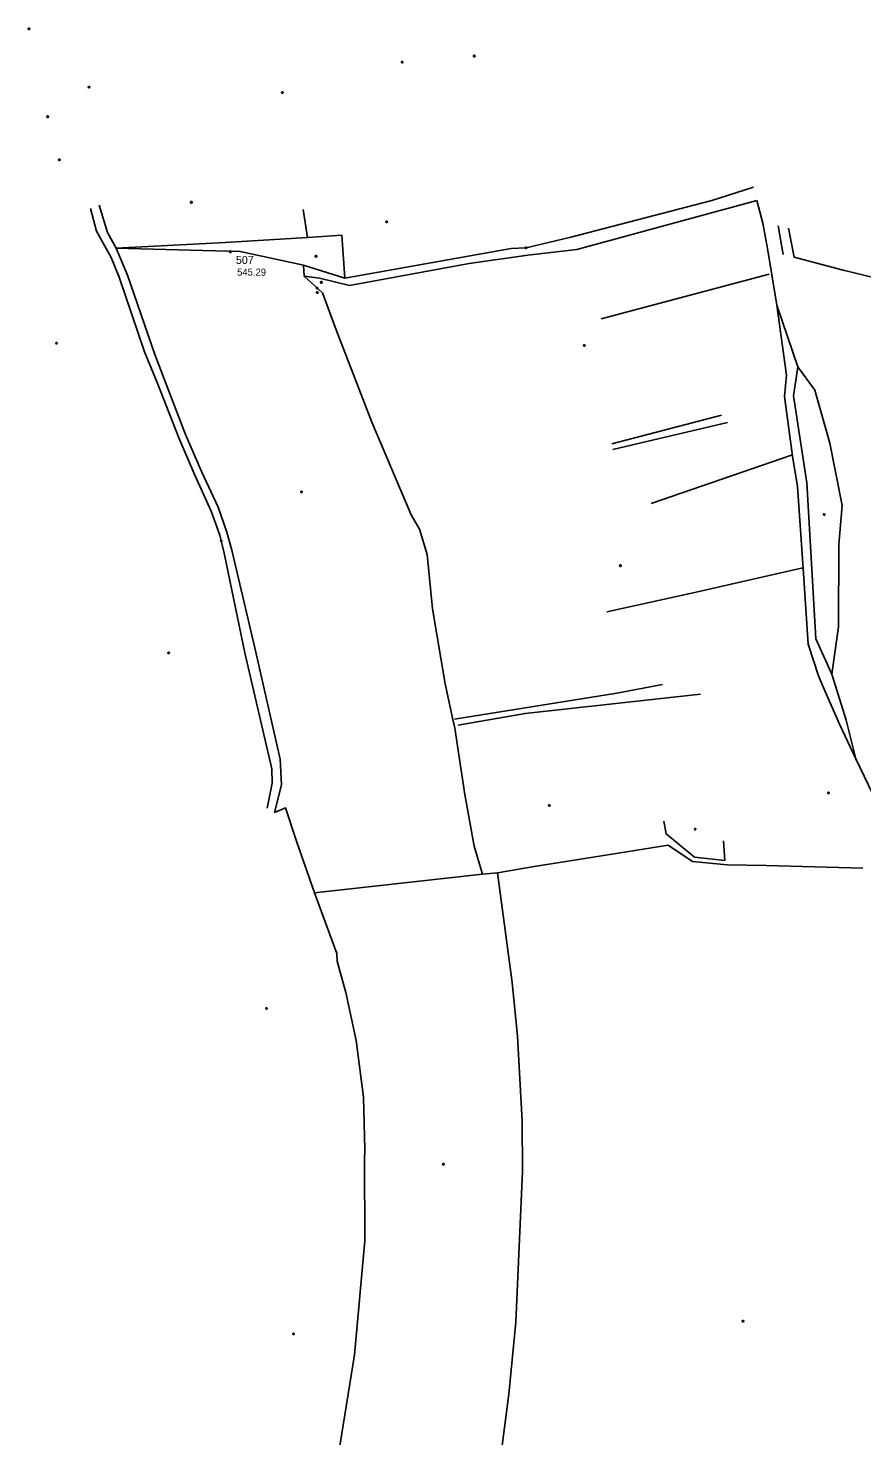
# Model space of a CAD drawing. Extents: x -664960 to -662754, y -993849 to -991145.
# Drawn here: x -664929 to -664575, y -992665 to -992067 of the extents above; entities that cross this region are included whole.
import ezdxf

# ---------------------------------------------------------------- set-up
doc = ezdxf.new("R2010")
doc.units = 0
for name, color, linetype in [('Vrstva 1', 7, 'Continuous'), ('Vrstva 12', 7, 'Continuous'), ('Vrstva 13', 7, 'Continuous'), ('Vrstva 18', 7, 'Continuous'), ('Vrstva 27', 7, 'Continuous'), ('Vrstva 63', 7, 'Continuous'), ('Vrstva 8', 7, 'Continuous')]:
    doc.layers.add(name, color=color, linetype=linetype)

msp = doc.modelspace()

# ---------------------------------------------------------------- linework, layer by layer
at = {"layer": 'Vrstva 12'}
msp.add_lwpolyline([(-664633.39, -992412.62), (-664632.92, -992420.96), (-664645.75, -992419.52), (-664657.83, -992409.7), (-664658.84, -992404.28)], dxfattribs=at)
at = {"layer": 'Vrstva 13'}
for points in [[(-664859.402, -992141.158), (-664859.222, -992141.458), (-664859.402, -992141.758), (-664859.762, -992141.758), (-664859.942, -992141.458), (-664859.762, -992141.158), (-664859.402, -992141.158)], [(-664776.425, -992149.44), (-664776.245, -992149.74), (-664776.425, -992150.04), (-664776.785, -992150.04), (-664776.965, -992149.74), (-664776.785, -992149.44), (-664776.425, -992149.44)], [(-664806.436, -992164.089), (-664806.256, -992164.389), (-664806.436, -992164.689), (-664806.796, -992164.689), (-664806.976, -992164.389), (-664806.796, -992164.089), (-664806.436, -992164.089)], [(-664916.702, -992201.007), (-664916.522, -992201.307), (-664916.702, -992201.607), (-664917.062, -992201.607), (-664917.242, -992201.307), (-664917.062, -992201.007), (-664916.702, -992201.007)], [(-664692.397, -992201.93), (-664692.217, -992202.23), (-664692.397, -992202.53), (-664692.757, -992202.53), (-664692.937, -992202.23), (-664692.757, -992201.93), (-664692.397, -992201.93)], [(-664812.636, -992264.155), (-664812.456, -992264.455), (-664812.636, -992264.755), (-664812.996, -992264.755), (-664813.176, -992264.455), (-664812.996, -992264.155), (-664812.636, -992264.155)], [(-664590.513, -992273.723), (-664590.333, -992274.023), (-664590.513, -992274.323), (-664590.873, -992274.323), (-664591.053, -992274.023), (-664590.873, -992273.723), (-664590.513, -992273.723)], [(-664677.083, -992295.481), (-664676.903, -992295.781), (-664677.083, -992296.081), (-664677.443, -992296.081), (-664677.623, -992295.781), (-664677.443, -992295.481), (-664677.083, -992295.481)], [(-664869.072, -992332.531), (-664868.892, -992332.831), (-664869.072, -992333.131), (-664869.432, -992333.131), (-664869.612, -992332.831), (-664869.432, -992332.531), (-664869.072, -992332.531)], [(-664588.659, -992392.01), (-664588.479, -992392.31), (-664588.659, -992392.61), (-664589.019, -992392.61), (-664589.199, -992392.31), (-664589.019, -992392.01), (-664588.659, -992392.01)], [(-664707.279, -992397.311), (-664707.099, -992397.611), (-664707.279, -992397.911), (-664707.639, -992397.911), (-664707.819, -992397.611), (-664707.639, -992397.311), (-664707.279, -992397.311)], [(-664645.282, -992407.384), (-664645.102, -992407.684), (-664645.282, -992407.984), (-664645.642, -992407.984), (-664645.822, -992407.684), (-664645.642, -992407.384), (-664645.282, -992407.384)], [(-664827.504, -992483.539), (-664827.324, -992483.839), (-664827.504, -992484.139), (-664827.864, -992484.139), (-664828.044, -992483.839), (-664827.864, -992483.539), (-664827.504, -992483.539)], [(-664752.295, -992549.705), (-664752.115, -992550.005), (-664752.295, -992550.305), (-664752.655, -992550.305), (-664752.835, -992550.005), (-664752.655, -992549.705), (-664752.295, -992549.705)], [(-664624.976, -992616.363), (-664624.796, -992616.663), (-664624.976, -992616.963), (-664625.336, -992616.963), (-664625.516, -992616.663), (-664625.336, -992616.363), (-664624.976, -992616.363)], [(-664816.029, -992621.761), (-664815.849, -992622.061), (-664816.029, -992622.361), (-664816.389, -992622.361), (-664816.569, -992622.061), (-664816.389, -992621.761), (-664816.029, -992621.761)]]:
    msp.add_lwpolyline(points, dxfattribs=at)
at = {"layer": 'Vrstva 18'}
for points in [[(-664928.417, -992067.487), (-664928.237, -992067.787), (-664928.417, -992068.087), (-664928.777, -992068.087), (-664928.957, -992067.787), (-664928.777, -992067.487), (-664928.417, -992067.487)], [(-664769.847, -992081.59), (-664769.667, -992081.89), (-664769.847, -992082.19), (-664770.207, -992082.19), (-664770.387, -992081.89), (-664770.207, -992081.59), (-664769.847, -992081.59)], [(-664739.194, -992079.012), (-664739.014, -992079.312), (-664739.194, -992079.612), (-664739.554, -992079.612), (-664739.734, -992079.312), (-664739.554, -992079.012), (-664739.194, -992079.012)], [(-664902.941, -992092.229), (-664902.761, -992092.529), (-664902.941, -992092.829), (-664903.301, -992092.829), (-664903.481, -992092.529), (-664903.301, -992092.229), (-664902.941, -992092.229)], [(-664820.732, -992094.56), (-664820.552, -992094.86), (-664820.732, -992095.16), (-664821.092, -992095.16), (-664821.272, -992094.86), (-664821.092, -992094.56), (-664820.732, -992094.56)], [(-664920.486, -992104.766), (-664920.306, -992105.066), (-664920.486, -992105.366), (-664920.846, -992105.366), (-664921.026, -992105.066), (-664920.846, -992104.766), (-664920.486, -992104.766)], [(-664915.52, -992123.094), (-664915.34, -992123.394), (-664915.52, -992123.694), (-664915.88, -992123.694), (-664916.06, -992123.394), (-664915.88, -992123.094), (-664915.52, -992123.094)], [(-664717.173, -992160.444), (-664716.993, -992160.744), (-664717.173, -992161.044), (-664717.533, -992161.044), (-664717.713, -992160.744), (-664717.533, -992160.444), (-664717.173, -992160.444)], [(-664805.943, -992177.566), (-664805.763, -992177.866), (-664805.943, -992178.166), (-664806.303, -992178.166), (-664806.483, -992177.866), (-664806.303, -992177.566), (-664805.943, -992177.566)], [(-664805.882, -992179.447), (-664805.702, -992179.747), (-664805.882, -992180.047), (-664806.242, -992180.047), (-664806.422, -992179.747), (-664806.242, -992179.447), (-664805.882, -992179.447)], [(-664846.769, -992284.901), (-664846.589, -992285.201), (-664846.769, -992285.501), (-664847.129, -992285.501), (-664847.309, -992285.201), (-664847.129, -992284.901), (-664846.769, -992284.901)]]:
    msp.add_lwpolyline(points, dxfattribs=at)
at = {"layer": 'Vrstva 27'}
for p, q in [((-664608.14, -992163.55), (-664610.152, -992151.496)), ((-664811.88, -992168.19), (-664794.408, -992173.708)), ((-664747.721, -992360.973), (-664678.737, -992349.924)), ((-664678.737, -992349.924), (-664659.319, -992346.292))]:
    msp.add_line(p, q, dxfattribs=at)
for points in [[(-664620.644, -992135.062), (-664638.455, -992140.655), (-664698.27, -992156.268), (-664717.353, -992160.744), (-664723.638, -992161.079), (-664794.408, -992173.708)], [(-664792.35, -992176.82), (-664741.572, -992167.435), (-664716.668, -992163.93), (-664695.802, -992161.463), (-664619.265, -992140.71)], [(-664827.42, -992398.84), (-664825.31, -992388.14), (-664825.36, -992382.06), (-664836.85, -992332.81), (-664845.66, -992290.42), (-664847.45, -992282.81), (-664851.17, -992272.64), (-664858.17, -992257.29), (-664864.97, -992241.43), (-664874.17, -992217.93), (-664879.57, -992204.91), (-664890.28, -992173.28), (-664893.73, -992164.91), (-664899.95, -992153.67), (-664902.47, -992144.03)], [(-664898.8, -992142.66), (-664895.19, -992154.22), (-664891.61, -992160.96), (-664886.7, -992172.35), (-664875.19, -992205.63), (-664870.94, -992216.91), (-664862.03, -992240.14), (-664855.16, -992256.06), (-664848.26, -992270.87), (-664844.53, -992281.59), (-664842.34, -992289.21), (-664832.62, -992330.65), (-664821.85, -992378), (-664821.28, -992388.93), (-664824.21, -992400.64)], [(-664792.35, -992176.82), (-664805.16, -992173.73), (-664811.68, -992172.83)], [(-664587.41, -992341.82), (-664594.17, -992326.88), (-664596.01, -992294.89), (-664598.04, -992260.62), (-664603.69, -992223.59), (-664601.86, -992211.31)], [(-664746.219, -992363.549), (-664717.751, -992358.539), (-664643.234, -992350.417)]]:
    msp.add_lwpolyline(points, dxfattribs=at)
at = {"layer": 'Vrstva 63'}
for p, q in [((-664616.743, -992150.243), (-664619.265, -992140.71)), ((-664811.88, -992168.19), (-664811.68, -992172.83)), ((-664614.045, -992171.988), (-664685.434, -992190.966)), ((-664680.872, -992244.01), (-664634.339, -992231.912)), ((-664680.434, -992246.511), (-664631.798, -992234.941)), ((-664604.503, -992248.796), (-664664.201, -992269.37)), ((-664599.772, -992296.748), (-664646.284, -992307.378)), ((-664646.284, -992307.378), (-664683.038, -992315.402)), ((-664807.2, -992434.68), (-664735.93, -992426.79))]:
    msp.add_line(p, q, dxfattribs=at)
for points in [[(-664605.758, -992152.436), (-664603.44, -992164.79), (-664582.56, -992170.22), (-664560.41, -992175.65), (-664523.07, -992182.99), (-664503.85, -992184.99), (-664486, -992184.34), (-664487.26, -992165.81), (-664493.84, -992134.78), (-664494.44, -992121.04)], [(-664891.61, -992160.96), (-664845.2, -992158.48), (-664810.2, -992156.37), (-664812.02, -992144.51)], [(-664561.39, -992410.84), (-664577.14, -992377.84), (-664584.17, -992363.13), (-664591.25, -992346.91), (-664593.11, -992342.57), (-664597.46, -992329.17), (-664599.63, -992297.04), (-664601.98, -992262.14), (-664604.17, -992249.32), (-664607.47, -992223.96), (-664606.69, -992214.91), (-664610.84, -992185.08), (-664614.74, -992161.03), (-664616.743, -992150.243)], [(-664810.2, -992156.37), (-664795.71, -992155.36), (-664794.408, -992173.708)], [(-664891.61, -992160.96), (-664838.87, -992162.39), (-664811.88, -992168.19)], [(-664811.68, -992172.83), (-664803.87, -992179.96), (-664798.08, -992195.68), (-664782.84, -992234.79), (-664766.25, -992274.22), (-664762.6, -992280.27), (-664759.32, -992291.07), (-664757.09, -992314.12), (-664751.73, -992345.99), (-664748.42, -992361.17), (-664747.56, -992364.82), (-664743.36, -992392.92), (-664739.41, -992414.9), (-664735.93, -992426.79), (-664729.45, -992426.22), (-664713.86, -992423.57), (-664692.31, -992420.16), (-664656.99, -992414.51), (-664646.58, -992421.37), (-664631.9, -992422.8), (-664615.3, -992423.09), (-664574.18, -992424.19)], [(-664804.15, -992175.15), (-664803.97, -992175.45), (-664804.15, -992175.75), (-664804.51, -992175.75), (-664804.69, -992175.45), (-664804.51, -992175.15), (-664804.15, -992175.15)], [(-664610.84, -992185.08), (-664601.86, -992211.31), (-664594.66, -992221.2), (-664588.32, -992243.8), (-664583.07, -992270.25), (-664584.48, -992286.78), (-664584.55, -992321.8), (-664587.41, -992341.82), (-664581.33, -992361.44), (-664577.14, -992377.84)], [(-664800.96, -992712.82), (-664797.02, -992673.16), (-664790.26, -992630.94), (-664785.81, -992582.58), (-664786.07, -992548.06), (-664785.94, -992543.77), (-664786.47, -992521.58), (-664789.59, -992497.46), (-664794, -992477.1), (-664797.68, -992463.73), (-664797.77, -992460.54), (-664807.2, -992434.68), (-664814.81, -992413.16), (-664819.55, -992398.64), (-664824.21, -992400.64)], [(-664740.88, -992771.61), (-664732.98, -992711.95), (-664724.72, -992647.59), (-664721.69, -992617.04), (-664718.92, -992552.98), (-664719.06, -992531.76), (-664721.04, -992495.55), (-664723.27, -992472.75), (-664729.45, -992426.22)]]:
    msp.add_lwpolyline(points, dxfattribs=at)
at = {"layer": 'Vrstva 8'}
msp.add_lwpolyline([(-664842.88, -992162.13), (-664842.7, -992162.43), (-664842.88, -992162.73), (-664843.24, -992162.73), (-664843.42, -992162.43), (-664843.24, -992162.13), (-664842.88, -992162.13)], dxfattribs=at)

# ---------------------------------------------------------------- texts
at = {"layer": 'Vrstva 1'}
msp.add_text('507', height=3.4, dxfattribs=at).set_placement((-664840.66, -992167.63))
at = {"layer": 'Vrstva 63'}
msp.add_text('545.29', height=3, dxfattribs=at).set_placement((-664840.136, -992172.61))

doc.saveas('drawing.dxf')
